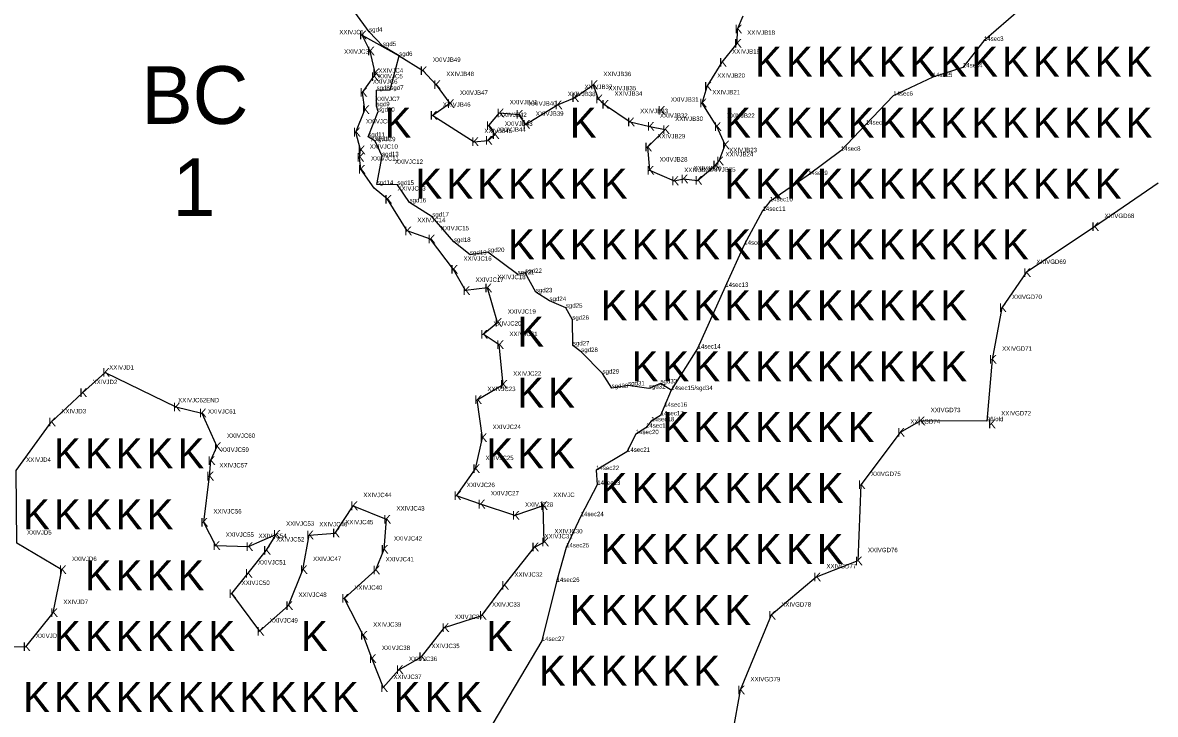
# Model space of a CAD drawing. Extents: x 2072529 to 2268812, y 436423 to 470008.
# Drawn here: x 2262793 to 2264077, y 441873 to 442657 of the extents above; entities that cross this region are included whole.
import ezdxf

# ---------------------------------------------------------------- set-up
doc = ezdxf.new("R2010")
doc.units = 0
for name, color, linetype in [('Old_Level_10', 7, 'Continuous'), ('Old_Level_20', 7, 'Continuous'), ('Old_Level_52', 7, 'Continuous'), ('Old_Level_55', 7, 'Continuous'), ('Old_Level_60', 7, 'Continuous'), ('Old_Level_62', 7, 'Continuous')]:
    doc.layers.add(name, color=color, linetype=linetype)

msp = doc.modelspace()

# ---------------------------------------------------------------- linework, layer by layer
at = {"layer": 'Old_Level_10'}
for points in [[(2263528.032, 442240.65), (2263515.735, 442248.255), (2263502.646, 442242.344), (2263479.106, 442245.86), (2263460.429, 442242.92), (2263450.02, 442259.32), (2263425.931, 442283.846), (2263416.374, 442291.223), (2263415.858, 442320.312), (2263408.495, 442333.958), (2263389.961, 442341.592), (2263374.449, 442351.452), (2263362.509, 442373.373), (2263353.901, 442371.718), (2263320.095, 442397.07), (2263299.847, 442394.066), (2263281.685, 442408.496), (2263257.076, 442437.086), (2263231.327, 442453.36), (2263217.506, 442473.141), (2263194.13, 442473.456), (2263200.214, 442505.64), (2263192.296, 442522.765), (2263184.537, 442527.661), (2263195.717, 442556.141), (2263193.732, 442562.271), (2263193.905, 442580.582), (2263209.512, 442580.758), (2263219.648, 442619.26), (2263201.101, 442630.387), (2263185.515, 442646.712), (2263169.422, 442668.768)], [(2263924.019, 442672.501), (2263882.334, 442636.318), (2263858.494, 442606.214), (2263824.346, 442595.249), (2263779.597, 442574.159), (2263748.504, 442541.402), (2263720.196, 442511.783), (2263683.101, 442484.3), (2263639.63, 442454.476), (2263631.337, 442443.68), (2263610.707, 442405.256), (2263589.23, 442357.569), (2263557.848, 442287.71), (2263528.032, 442240.65), (2263519.865, 442221.793), (2263515.897, 442211.998), (2263505.206, 442205.265), (2263499.32, 442197.979), (2263487.638, 442190.693), (2263477.78, 442170.671), (2263442.743, 442150.008), (2263444.095, 442133.265), (2263425.301, 442097.754), (2263408.784, 442062.427), (2263397.909, 442023.272), (2263381.116, 441956.406)], [(2263381.116, 441956.406), (2263319.774, 441852.833), (2263265.308, 441807.413), (2263142.761, 441712.033), (2263024.752, 441607.568), (2262870.433, 441480.394), (2262729.73, 441316.884), (2262602.644, 441135.207), (2262511.868, 440980.781), (2262461.941, 440849.064), (2262404.532, 440738.7), (2262380.386, 440683.933)]]:
    msp.add_lwpolyline(points, dxfattribs=at)
at = {"layer": 'Old_Level_20'}
for p, q in [((2263185.515, 442646.712), (2263185.515, 442646.712)), ((2263201.101, 442630.387), (2263201.101, 442630.387)), ((2263201.101, 442630.387), (2263201.101, 442630.387)), ((2263882.334, 442636.318), (2263882.334, 442636.318)), ((2263219.648, 442619.26), (2263219.648, 442619.26)), ((2263858.494, 442606.214), (2263858.494, 442606.214)), ((2263824.346, 442595.249), (2263824.346, 442595.249)), ((2263193.905, 442580.582), (2263193.905, 442580.582)), ((2263209.512, 442580.758), (2263209.512, 442580.758)), ((2263209.512, 442580.758), (2263209.512, 442580.758)), ((2263779.597, 442574.159), (2263779.597, 442574.159)), ((2263193.732, 442562.271), (2263193.732, 442562.271)), ((2263193.732, 442562.271), (2263193.732, 442562.271)), ((2263195.717, 442556.141), (2263195.717, 442556.141)), ((2263748.504, 442541.402), (2263748.504, 442541.402)), ((2263184.537, 442527.661), (2263184.537, 442527.661)), ((2263184.537, 442527.661), (2263184.537, 442527.661)), ((2263192.296, 442522.765), (2263192.296, 442522.765)), ((2263200.214, 442505.64), (2263200.214, 442505.64)), ((2263200.214, 442505.64), (2263200.214, 442505.64)), ((2263720.196, 442511.783), (2263720.196, 442511.783)), ((2263683.101, 442484.3), (2263683.101, 442484.3)), ((2263194.13, 442473.456), (2263194.13, 442473.456)), ((2263217.506, 442473.141), (2263217.506, 442473.141)), ((2263217.506, 442473.141), (2263217.506, 442473.141)), ((2263231.327, 442453.36), (2263231.327, 442453.36)), ((2263639.63, 442454.476), (2263639.63, 442454.476)), ((2263631.337, 442443.68), (2263631.337, 442443.68)), ((2263257.076, 442437.086), (2263257.076, 442437.086)), ((2263257.076, 442437.086), (2263257.076, 442437.086)), ((2263281.685, 442408.496), (2263281.685, 442408.496)), ((2263610.707, 442405.256), (2263610.707, 442405.256)), ((2263299.847, 442394.066), (2263299.847, 442394.066)), ((2263299.847, 442394.066), (2263299.847, 442394.066)), ((2263320.095, 442397.07), (2263320.095, 442397.07)), ((2263362.509, 442373.373), (2263362.509, 442373.373)), ((2263353.901, 442371.718), (2263353.901, 442371.718)), ((2263353.901, 442371.718), (2263353.901, 442371.718)), ((2263374.449, 442351.452), (2263374.449, 442351.452)), ((2263374.449, 442351.452), (2263374.449, 442351.452)), ((2263589.23, 442357.569), (2263589.23, 442357.569)), ((2263389.961, 442341.592), (2263389.961, 442341.592)), ((2263408.495, 442333.958), (2263408.495, 442333.958)), ((2263408.495, 442333.958), (2263408.495, 442333.958)), ((2263415.858, 442320.312), (2263415.858, 442320.312)), ((2263416.374, 442291.223), (2263416.374, 442291.223)), ((2263416.374, 442291.223), (2263416.374, 442291.223)), ((2263425.931, 442283.846), (2263425.931, 442283.846)), ((2263557.848, 442287.71), (2263557.848, 442287.71)), ((2263450.02, 442259.32), (2263450.02, 442259.32)), ((2263450.02, 442259.32), (2263450.02, 442259.32)), ((2263479.106, 442245.86), (2263479.106, 442245.86)), ((2263479.106, 442245.86), (2263479.106, 442245.86)), ((2263515.735, 442248.255), (2263515.735, 442248.255)), ((2263515.735, 442248.255), (2263515.735, 442248.255)), ((2263460.429, 442242.92), (2263460.429, 442242.92)), ((2263502.646, 442242.344), (2263502.646, 442242.344)), ((2263528.032, 442240.65), (2263528.032, 442240.65)), ((2263519.865, 442221.793), (2263519.865, 442221.793)), ((2263515.897, 442211.998), (2263515.897, 442211.998)), ((2263499.32, 442197.979), (2263499.32, 442197.979)), ((2263505.206, 442205.265), (2263505.206, 442205.265)), ((2263885.589, 442205.395), (2263885.589, 442205.395)), ((2263885.589, 442205.395), (2263885.589, 442205.395)), ((2263487.638, 442190.693), (2263487.638, 442190.693)), ((2263477.78, 442170.671), (2263477.78, 442170.671)), ((2263442.743, 442150.008), (2263442.743, 442150.008)), ((2263444.095, 442133.265), (2263444.095, 442133.265)), ((2263425.301, 442097.754), (2263425.301, 442097.754)), ((2263408.784, 442062.427), (2263408.784, 442062.427)), ((2263397.909, 442023.272), (2263397.909, 442023.272)), ((2263381.116, 441956.406), (2263381.116, 441956.406))]:
    msp.add_line(p, q, dxfattribs=at)
at = {"layer": 'Old_Level_52'}
msp.add_line((2262886.314, 442260.671), (2262966.477, 442221.501), dxfattribs=at)
for points in [[(2263219.648, 442619.26), (2263246.257, 442602.649), (2263261.444, 442586.537), (2263277.077, 442565.241), (2263257.55, 442551.855), (2263304.528, 442521.967), (2263319.997, 442523.525), (2263327.822, 442530.165), (2263321.142, 442540.247), (2263333.406, 442554.598), (2263354.994, 442553.056), (2263362.884, 442541.576), (2263399.18, 442563.814), (2263418.153, 442571.908), (2263439.541, 442586.488), (2263445.256, 442570.444), (2263452.156, 442564.266), (2263481.266, 442544.529), (2263503.596, 442539.342), (2263520.971, 442535.766), (2263500.883, 442515.969), (2263503.389, 442489.723), (2263531.168, 442477.728), (2263541.87, 442479.818), (2263557.848, 442478.151), (2263577.956, 442495.49), (2263582.188, 442500.287), (2263588.874, 442518.339), (2263579.537, 442539.263), (2263563.031, 442565.845), (2263568.563, 442584.732), (2263585.489, 442612.032), (2263602.536, 442633.397), (2263603.071, 442649.581), (2263609.458, 442664.489)], [(2262966.477, 442221.501), (2262995.854, 442214.556), (2263012.882, 442176.656), (2263005.828, 442160.79), (2263004.263, 442143.096), (2262997.59, 442090.947), (2263011.484, 442064.53), (2263048.702, 442063.264), (2263079.909, 442077.05), (2263068.682, 442059.218), (2263047.924, 442033.168), (2263029.446, 442010.039), (2263061.31, 441967.384), (2263093.964, 441996.469), (2263110.483, 442037.151), (2263117.478, 442076.318), (2263146.913, 442078.697), (2263167.435, 442109.487), (2263204.981, 442094.323), (2263202.067, 442060.206), (2263192.779, 442036.695), (2263157.13, 442004.602), (2263178.596, 441962.713), (2263188.478, 441936.308), (2263201.562, 441903.503), (2263219.105, 441923.802), (2263244.735, 441938.444), (2263271.014, 441971.463), (2263313.34, 441985.429), (2263338.711, 442019.369), (2263372.828, 442062.706), (2263384.082, 442068.464), (2263382.746, 442109.668), (2263350.781, 442098.562), (2263311.916, 442111.374), (2263284.643, 442120.852), (2263305.955, 442151.469), (2263314.059, 442186.626), (2263308.104, 442229.615), (2263337.274, 442247.023), (2263333.078, 442291.931), (2263314.751, 442303.873), (2263331.113, 442317.308), (2263319.508, 442356.416), (2263294.699, 442353.397), (2263281.021, 442377.344), (2263255.233, 442411.809), (2263228.665, 442421.019), (2263206.211, 442456.819), (2263191.169, 442469.245), (2263176.054, 442490.805), (2263174.679, 442504.283), (2263175.87, 442512.738), (2263170.371, 442532.862), (2263180.749, 442558.207), (2263178.137, 442577.895), (2263191.021, 442595.835), (2263192.422, 442600.142), (2263186.559, 442624.69), (2263177.465, 442642.931), (2263219.648, 442619.26)], [(2264079.973, 442475.208), (2264007.538, 442425.746), (2263930.275, 442373.748), (2263902.729, 442333.909), (2263891.512, 442275.343), (2263885.589, 442205.395), (2263810.514, 442205.747), (2263787.43, 442192.676), (2263742.824, 442133.355), (2263739.393, 442047.105), (2263692.368, 442028.848), (2263641.174, 441985.478), (2263606.237, 441900.731), (2263597.487, 441852.349)], [(2262743.472, 441950.735), (2262796.215, 441949.93), (2262827.452, 441988.336), (2262837.222, 442037.063), (2262786.143, 442067.04), (2262785.27, 442149.425), (2262825.149, 442204.408), (2262860.516, 442237.548), (2262886.314, 442260.671)]]:
    msp.add_lwpolyline(points, dxfattribs=at)

# ---------------------------------------------------------------- texts
at = {"layer": 'Old_Level_20'}
for p in [(2263174.211, 442638.009), (2263599.817, 442644.659), (2263599.282, 442628.475), (2263183.305, 442619.768), (2263189.168, 442595.22), (2263243.003, 442597.727), (2263582.235, 442607.11), (2263187.767, 442590.913), (2263174.883, 442572.973), (2263258.19, 442581.615), (2263436.287, 442581.566), (2263565.309, 442579.81), (2263273.823, 442560.319), (2263395.926, 442558.892), (2263414.899, 442566.986), (2263442.002, 442565.522), (2263448.902, 442559.344), (2263559.777, 442560.923), (2263177.495, 442553.285), (2263254.296, 442546.933), (2263330.152, 442549.676), (2263351.74, 442548.134), (2263512.645, 442552.602), (2263317.888, 442535.325), (2263359.63, 442536.654), (2263478.012, 442539.607), (2263500.342, 442534.42), (2263517.717, 442530.844), (2263576.283, 442534.341), (2263167.117, 442527.94), (2263316.743, 442518.603), (2263324.568, 442525.243), (2263172.616, 442507.816), (2263301.274, 442517.045), (2263497.629, 442511.047), (2263585.62, 442513.417), (2263585.62, 442513.417), (2263171.425, 442499.361), (2263578.934, 442495.365), (2263172.8, 442485.883), (2263500.135, 442484.801), (2263574.702, 442490.568), (2263527.914, 442472.806), (2263538.616, 442474.896), (2263554.594, 442473.229), (2263202.957, 442451.897), (2263225.411, 442416.097), (2264004.284, 442420.824), (2263251.979, 442406.887), (2263277.767, 442372.422), (2263927.021, 442368.826), (2263316.254, 442351.494), (2263291.445, 442348.475), (2263899.475, 442328.987), (2263327.859, 442312.386), (2263311.497, 442298.951), (2263329.824, 442287.009), (2263888.258, 442270.421), (2262883.06, 442255.749), (2263334.02, 442242.101), (2262857.262, 442232.626), (2263304.85, 442224.693), (2262963.223, 442216.579), (2262992.6, 442209.634), (2262821.895, 442199.486), (2263807.26, 442200.825), (2263887.185, 442197.121), (2263784.176, 442187.754), (2263009.628, 442171.734), (2263310.805, 442181.704), (2263002.574, 442155.868), (2263302.701, 442146.547), (2263001.009, 442138.174), (2263739.57, 442128.433), (2263281.389, 442115.93), (2263164.181, 442104.565), (2263308.662, 442106.452), (2263379.492, 442104.746), (2262994.336, 442086.025), (2263201.727, 442089.401), (2263347.527, 442093.64), (2263076.655, 442072.128), (2263114.224, 442071.396), (2263143.659, 442073.775), (2263008.23, 442059.608), (2263045.448, 442058.342), (2263369.574, 442057.784), (2263380.828, 442063.542), (2263065.428, 442054.296), (2263198.813, 442055.284), (2262833.968, 442032.141), (2263107.229, 442032.229), (2263189.525, 442031.773), (2263736.139, 442042.183), (2263044.67, 442028.246), (2263689.114, 442023.926), (2263026.192, 442005.117), (2263335.457, 442014.447), (2263090.71, 441991.547), (2263153.876, 441999.68), (2262824.198, 441983.414), (2263310.086, 441980.507), (2263637.92, 441980.556), (2263267.76, 441966.541), (2263058.056, 441962.462), (2263175.342, 441957.791), (2262792.961, 441945.008), (2263185.224, 441931.386), (2263241.481, 441933.522), (2263215.851, 441918.88), (2263198.308, 441898.581), (2263602.983, 441895.809)]:
    msp.add_text('K', height=9.843, dxfattribs=at).set_placement(p)
at = {"layer": 'Old_Level_55'}
for p in [(2263622.992, 442595.632), (2263657.992, 442595.632), (2263692.992, 442595.632), (2263727.992, 442595.632), (2263762.992, 442595.632), (2263797.992, 442595.632), (2263832.992, 442595.632), (2263867.992, 442595.632), (2263902.992, 442595.632), (2263937.992, 442595.632), (2263972.992, 442595.632), (2264007.992, 442595.632), (2264042.992, 442595.632), (2263202.992, 442526.632), (2263412.992, 442526.632), (2263587.992, 442526.632), (2263622.992, 442526.632), (2263657.992, 442526.632), (2263692.992, 442526.632), (2263727.992, 442526.632), (2263762.992, 442526.632), (2263797.992, 442526.632), (2263832.992, 442526.632), (2263867.992, 442526.632), (2263902.992, 442526.632), (2263937.992, 442526.632), (2263972.992, 442526.632), (2264007.992, 442526.632), (2264042.992, 442526.632), (2263237.992, 442457.632), (2263272.992, 442457.632), (2263307.992, 442457.632), (2263342.992, 442457.632), (2263377.992, 442457.632), (2263412.992, 442457.632), (2263447.992, 442457.632), (2263587.992, 442457.632), (2263622.992, 442457.632), (2263657.992, 442457.632), (2263692.992, 442457.632), (2263727.992, 442457.632), (2263762.992, 442457.632), (2263797.992, 442457.632), (2263832.992, 442457.632), (2263867.992, 442457.632), (2263902.992, 442457.632), (2263937.992, 442457.632), (2263972.992, 442457.632), (2264007.992, 442457.632), (2263342.992, 442388.632), (2263377.992, 442388.632), (2263412.992, 442388.632), (2263447.992, 442388.632), (2263482.992, 442388.632), (2263517.992, 442388.632), (2263552.992, 442388.632), (2263587.992, 442388.632), (2263622.992, 442388.632), (2263657.992, 442388.632), (2263692.992, 442388.632), (2263727.992, 442388.632), (2263762.992, 442388.632), (2263797.992, 442388.632), (2263832.992, 442388.632), (2263867.992, 442388.632), (2263902.992, 442388.632), (2263447.992, 442319.632), (2263482.992, 442319.632), (2263517.992, 442319.632), (2263552.992, 442319.632), (2263587.992, 442319.632), (2263622.992, 442319.632), (2263657.992, 442319.632), (2263692.992, 442319.632), (2263727.992, 442319.632), (2263762.992, 442319.632), (2263797.992, 442319.632), (2263832.992, 442319.632), (2263353.361, 442289.888), (2263482.992, 442250.632), (2263517.992, 442250.632), (2263552.992, 442250.632), (2263587.992, 442250.632), (2263622.992, 442250.632), (2263657.992, 442250.632), (2263692.992, 442250.632), (2263727.992, 442250.632), (2263762.992, 442250.632), (2263797.992, 442250.632), (2263832.992, 442250.632), (2263353.361, 442220.888), (2263388.361, 442220.888), (2263517.992, 442181.632), (2263552.992, 442181.632), (2263587.992, 442181.632), (2263622.992, 442181.632), (2263657.992, 442181.632), (2263692.992, 442181.632), (2263727.992, 442181.632), (2262828.361, 442151.888), (2262863.361, 442151.888), (2262898.361, 442151.888), (2262933.361, 442151.888), (2262968.361, 442151.888), (2263318.361, 442151.888), (2263353.361, 442151.888), (2263388.361, 442151.888), (2263447.992, 442112.632), (2263482.992, 442112.632), (2263517.992, 442112.632), (2263552.992, 442112.632), (2263587.992, 442112.632), (2263622.992, 442112.632), (2263657.992, 442112.632), (2263692.992, 442112.632), (2262793.361, 442082.888), (2262828.361, 442082.888), (2262863.361, 442082.888), (2262898.361, 442082.888), (2262933.361, 442082.888), (2263447.992, 442043.632), (2263482.992, 442043.632), (2263517.992, 442043.632), (2263552.992, 442043.632), (2263587.992, 442043.632), (2263622.992, 442043.632), (2263657.992, 442043.632), (2263692.992, 442043.632), (2262863.361, 442013.888), (2262898.361, 442013.888), (2262933.361, 442013.888), (2262968.361, 442013.888), (2263412.992, 441974.632), (2263447.992, 441974.632), (2263482.992, 441974.632), (2263517.992, 441974.632), (2263552.992, 441974.632), (2263587.992, 441974.632), (2262828.361, 441944.888), (2262863.361, 441944.888), (2262898.361, 441944.888), (2262933.361, 441944.888), (2262968.361, 441944.888), (2263003.361, 441944.888), (2263108.361, 441944.888), (2263318.361, 441944.888), (2263377.992, 441905.632), (2263412.992, 441905.632), (2263447.992, 441905.632), (2263482.992, 441905.632), (2263517.992, 441905.632), (2263552.992, 441905.632), (2262793.361, 441875.888), (2262828.361, 441875.888), (2262863.361, 441875.888), (2262898.361, 441875.888), (2262933.361, 441875.888), (2262968.361, 441875.888), (2263003.361, 441875.888), (2263038.361, 441875.888), (2263073.361, 441875.888), (2263108.361, 441875.888), (2263143.361, 441875.888), (2263213.361, 441875.888), (2263248.361, 441875.888), (2263283.361, 441875.888)]:
    msp.add_text('K', height=34, dxfattribs=at).set_placement(p)
at = {"layer": 'Old_Level_60'}
for s, p in [('XXIVJC1 ', (2263151.722, 442643.758)), ('sgd4', (2263185.515, 442646.712)), ('XXIVJB18 ', (2263614.046, 442643.239)), ('sgd5', (2263201.101, 442630.387)), ('sgd5', (2263201.101, 442630.387)), ('14sec3', (2263882.334, 442636.318)), ('XXIVJC3 ', (2263157.159, 442621.687)), ('sgd6', (2263219.648, 442619.26)), ('XXIVJB49 ', (2263257.767, 442612.491)), ('XXIVJB19 ', (2263596.998, 442621.874)), ('XXIVJC4 ', (2263196.083, 442600.232)), ('14sec4', (2263858.494, 442606.214)), ('XXIVJC6 ', (2263189.647, 442587.737)), ('XXIVJC5 ', (2263195.633, 442593.784)), ('XXIVJB48 ', (2263272.954, 442596.378)), ('XXIVJB36 ', (2263451.051, 442596.329)), ('XXIVJB20 ', (2263580.073, 442594.574)), ('14sec5', (2263824.346, 442595.249)), ('sgd8', (2263193.905, 442580.582)), ('sgd7', (2263209.512, 442580.758)), ('sgd7', (2263209.512, 442580.758)), ('XXIVJB47 ', (2263288.587, 442575.083)), ('XXIVJB37 ', (2263429.663, 442581.749)), ('XXIVJB35 ', (2263456.766, 442580.286)), ('XXIVJB34 ', (2263463.665, 442574.108)), ('XXIVJB21 ', (2263574.541, 442575.686)), ('14sec6', (2263779.597, 442574.159)), ('XXIVJC7 ', (2263192.258, 442568.049)), ('sgd9', (2263193.732, 442562.271)), ('sgd9', (2263193.732, 442562.271)), ('XXIVJB46 ', (2263269.059, 442561.697)), ('XXIVJB41 ', (2263344.916, 442564.44)), ('XXIVJB40 ', (2263366.503, 442562.898)), ('XXIVJB38 ', (2263410.69, 442573.655)), ('XXIVJB31 ', (2263527.409, 442567.366)), ('sgd10', (2263195.717, 442556.141)), ('XXIVJB42 ', (2263332.652, 442550.089)), ('XXIVJB39 ', (2263374.394, 442551.418)), ('XXIVJB33 ', (2263492.776, 442554.371)), ('XXIVJB32 ', (2263515.106, 442549.184)), ('XXIVJB22 ', (2263591.047, 442549.105)), ('XXIVJC8 ', (2263181.881, 442542.704)), ('XXIVJB43 ', (2263339.332, 442540.007)), ('XXIVJB30 ', (2263532.481, 442545.608)), ('14sec7', (2263748.504, 442541.402)), ('sgd11', (2263184.537, 442527.661)), ('sgd11', (2263184.537, 442527.661)), ('XXIVJC9 ', (2263187.38, 442522.579)), ('sgd12', (2263192.296, 442522.765)), ('XXIVJB45 ', (2263316.038, 442531.808)), ('XXIVJB44 ', (2263331.507, 442533.367)), ('XXIVJB29 ', (2263512.392, 442525.811)), ('XXIVJC10 ', (2263186.189, 442514.125)), ('XXIVJB23 ', (2263593.698, 442510.129)), ('14sec8', (2263720.196, 442511.783)), ('XXIVJC11 ', (2263187.564, 442500.647)), ('sgd13', (2263200.214, 442505.64)), ('sgd13', (2263200.214, 442505.64)), ('XXIVJC12 ', (2263214.781, 442496.927)), ('XXIVJB28 ', (2263514.899, 442499.564)), ('XXIVJB24 ', (2263589.466, 442505.332)), ('XXIVJB27 ', (2263542.678, 442487.57)), ('XXIVJB26 ', (2263553.38, 442489.66)), ('XXIVJB25 ', (2263569.357, 442487.993)), ('14sec9', (2263683.101, 442484.3)), ('sgd14', (2263194.13, 442473.456)), ('sgd15', (2263217.506, 442473.141)), ('sgd15', (2263217.506, 442473.141)), ('XXIVJC13 ', (2263217.721, 442466.661)), ('sgd16', (2263231.327, 442453.36)), ('14sec10', (2263639.63, 442454.476)), ('sgd17', (2263257.076, 442437.086)), ('sgd17', (2263257.076, 442437.086)), ('14sec11', (2263631.337, 442443.68)), ('XXIVGD68 ', (2264019.048, 442435.588)), ('XXIVJC14 ', (2263240.175, 442430.86)), ('XXIVJC15 ', (2263266.743, 442421.651)), ('sgd18', (2263281.685, 442408.496)), ('sgd19', (2263299.847, 442394.066)), ('sgd19', (2263299.847, 442394.066)), ('sgd20', (2263320.095, 442397.07)), ('14sce12', (2263610.707, 442405.256)), ('XXIVJC16 ', (2263292.53, 442387.186)), ('XXIVGD69 ', (2263941.784, 442383.59)), ('sgd21', (2263353.901, 442371.718)), ('sgd21', (2263353.901, 442371.718)), ('sgd22', (2263362.509, 442373.373)), ('XXIVJC17 ', (2263306.208, 442363.239)), ('XXIVJC18 ', (2263331.018, 442366.258)), ('14sec13', (2263589.23, 442357.569)), ('sgd23', (2263374.449, 442351.452)), ('sgd23', (2263374.449, 442351.452)), ('XXIVGD70 ', (2263914.239, 442343.751)), ('sgd24', (2263389.961, 442341.592)), ('sgd25', (2263408.495, 442333.958)), ('sgd25', (2263408.495, 442333.958)), ('XXIVJC19 ', (2263342.622, 442327.15)), ('sgd26', (2263415.858, 442320.312)), ('XXIVJC20 ', (2263326.261, 442313.715)), ('XXIVJC21 ', (2263344.587, 442301.773)), ('sgd27', (2263416.374, 442291.223)), ('sgd27', (2263416.374, 442291.223)), ('sgd28', (2263425.931, 442283.846)), ('14sec14', (2263557.848, 442287.71)), ('XXIVGD71 ', (2263903.021, 442285.185)), ('XXIVJD1 ', (2262890.887, 442263.862)), ('XXIVJC22 ', (2263348.784, 442256.865)), ('sgd29', (2263450.02, 442259.32)), ('sgd29', (2263450.02, 442259.32)), ('XXIVJD2 ', (2262872.026, 442247.39)), ('sgd30', (2263460.429, 442242.92)), ('sgd31', (2263479.106, 442245.86)), ('sgd31', (2263479.106, 442245.86)), ('sgd32', (2263502.646, 442242.344)), ('sgd33', (2263515.735, 442248.255)), ('sgd33', (2263515.735, 442248.255)), ('14sec15/sgd34', (2263528.032, 442240.65)), ('XXIVJC23 ', (2263319.614, 442239.457)), ('XXIVJD3 ', (2262836.659, 442214.25)), ('XXIVJC62END ', (2262969.028, 442226.716)), ('14sec16', (2263519.865, 442221.793)), ('XXIVGD73 ', (2263822.024, 442215.589)), ('XXIVJC61 ', (2263002.74, 442213.988)), ('14sec18', (2263505.206, 442205.265)), ('14sec17', (2263515.897, 442211.998)), ('XXIVGD74 ', (2263798.94, 442202.518)), ('96/old', (2263885.589, 442205.395)), ('96/old', (2263885.589, 442205.395)), ('XXIVGD72 ', (2263901.949, 442211.885)), ('XXIVJC24 ', (2263325.568, 442196.468)), ('14sec20', (2263487.638, 442190.693)), ('14sec19', (2263499.32, 442197.979)), ('XXIVJC60 ', (2263024.391, 442186.497)), ('XXIVJC59 ', (2263017.337, 442170.631)), ('14sec21', (2263477.78, 442170.671)), ('XXIVJD4 ', (2262796.78, 442159.267)), ('XXIVJC57 ', (2263015.773, 442152.938)), ('XXIVJC25 ', (2263317.465, 442161.31)), ('14sec22', (2263442.743, 442150.008)), ('XXIVGD75 ', (2263754.334, 442143.197)), ('XXIVJC26 ', (2263296.153, 442130.694)), ('14sec23', (2263444.095, 442133.265)), ('XXIVJC44 ', (2263178.945, 442119.329)), ('XXIVJC27 ', (2263323.426, 442121.215)), ('XXIVJC ', (2263394.256, 442119.509)), ('XXIVJC56 ', (2263009.099, 442100.789)), ('XXIVJC43 ', (2263216.491, 442104.165)), ('XXIVJC28 ', (2263362.291, 442108.404)), ('XXIVJC53 ', (2263091.419, 442086.891)), ('XXIVJC46 ', (2263128.988, 442086.16)), ('XXIVJC45 ', (2263158.423, 442088.538)), ('14sec24', (2263425.301, 442097.754)), ('XXIVJD5 ', (2262797.653, 442076.882)), ('XXIVJC55 ', (2263022.994, 442074.372)), ('XXIVJC54 ', (2263060.211, 442073.105)), ('XXIVJC30 ', (2263395.591, 442078.305)), ('XXIVJC52 ', (2263080.192, 442069.06)), ('XXIVJC42 ', (2263213.577, 442070.048)), ('XXIVJC31 ', (2263384.338, 442072.548)), ('14sec25', (2263408.784, 442062.427)), ('XXIVGD76 ', (2263750.902, 442056.947)), ('XXIVJD6 ', (2262848.732, 442046.905)), ('XXIVJC51 ', (2263059.434, 442043.01)), ('XXIVJC47 ', (2263121.993, 442046.993)), ('XXIVJC41 ', (2263204.289, 442046.537)), ('XXIVGD77 ', (2263703.878, 442038.689)), ('XXIVJC32 ', (2263350.221, 442029.211)), ('14sec26', (2263397.909, 442023.272)), ('XXIVJC50 ', (2263040.956, 442019.88)), ('XXIVJC40 ', (2263168.64, 442014.444)), ('XXIVJD7 ', (2262838.962, 441998.178)), ('XXIVJC48 ', (2263105.474, 442006.311)), ('XXIVJC33 ', (2263324.85, 441995.271)), ('XXIVGD78 ', (2263652.684, 441995.32)), ('XXIVJC49 ', (2263072.82, 441977.226)), ('XXIVJC39 ', (2263190.106, 441972.554)), ('XXIVJC34 ', (2263282.524, 441981.304)), ('XXIVJD8 ', (2262807.725, 441959.772)), ('XXIVJC38 ', (2263199.988, 441946.15)), ('XXIVJC35 ', (2263256.244, 441948.286)), ('14sec27', (2263381.116, 441956.406)), ('XXIVJC36 ', (2263230.615, 441933.644)), ('XXIVJC37 ', (2263213.072, 441913.345)), ('XXIVGD79 ', (2263617.746, 441910.573))]:
    msp.add_text(s, height=5, dxfattribs=at).set_placement(p)
at = {"layer": 'Old_Level_62'}
for s, p in [('BC', (2262927.197, 442542.244)), ('1', (2262962.674, 442437.7))]:
    msp.add_text(s, height=65.34, dxfattribs=at).set_placement(p)

doc.saveas('drawing.dxf')
